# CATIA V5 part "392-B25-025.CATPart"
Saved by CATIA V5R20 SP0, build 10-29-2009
Part number: 392-B25-025
Definition: NONE
Nomenclature: 392-B25-025
Source: Unknown
Description: 392-B25-025
Bounding box of the stored display mesh (mm): x 0 to 25, y -12.25 to 12.25, z -12.064 to 12.064
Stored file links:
  C:\Users\Utente\Desktop\IO LAVORO\3D X SITO CF\X SITO\3D files 392B\392-B25-025.CATPart
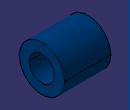
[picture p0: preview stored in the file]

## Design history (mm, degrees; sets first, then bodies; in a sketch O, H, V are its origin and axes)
Body1 "392-B25-025" (main body)
  Solid1: solid without history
